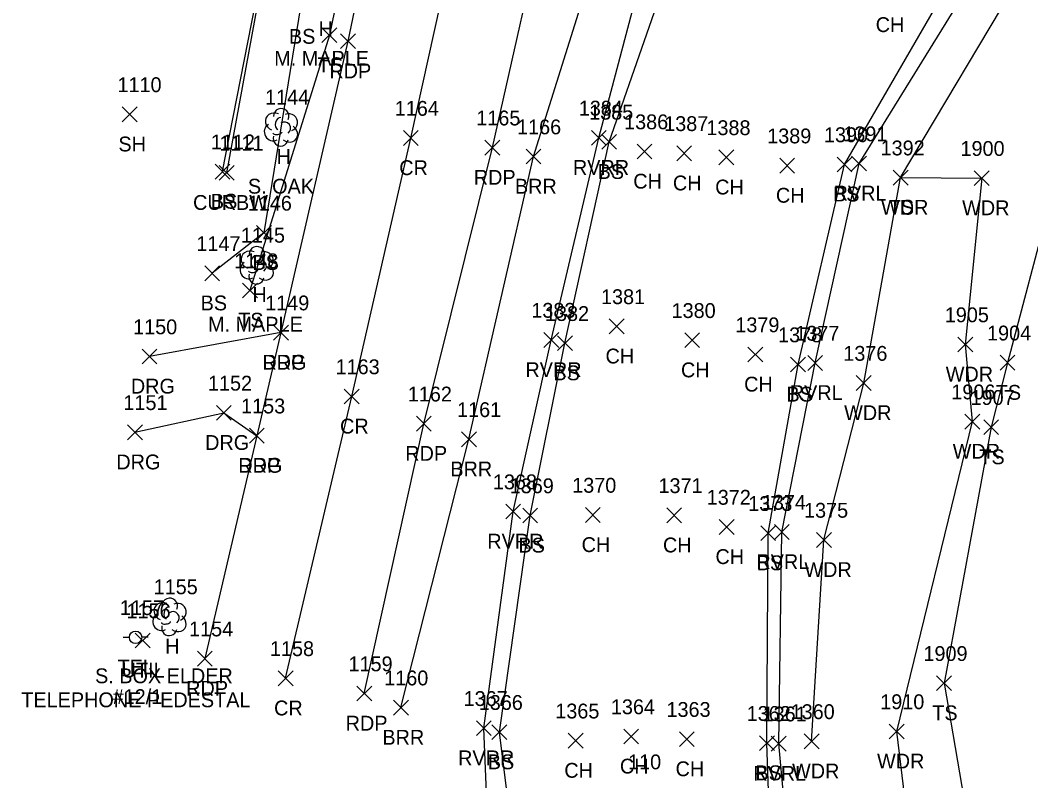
# Model space of a CAD drawing. Extents: x 1600395 to 1603269, y 874955 to 877143.
# Drawn here: x 1601626.7 to 1601763, y 875009.9 to 875112.5 of the extents above; entities that cross this region are included whole.
import ezdxf

# ---------------------------------------------------------------- set-up
doc = ezdxf.new("R2010")
doc.units = 0
for name, color, linetype in [('C_I', 7, 'Continuous'), ('L_A', 7, 'Continuous'), ('L_C', 7, 'Continuous'), ('L_I', 7, 'Continuous'), ('L_TIC', 7, 'Continuous'), ('LABL', 7, 'Continuous'), ('LAWA', 7, 'Continuous'), ('LAWE', 7, 'Continuous'), ('LELB', 7, 'Continuous'), ('LTD', 7, 'Continuous'), ('P_A', 7, 'Continuous'), ('P_I', 7, 'Continuous'), ('P_TIC', 7, 'Continuous'), ('PET', 7, 'Continuous'), ('PRC', 7, 'Continuous'), ('R_A', 7, 'Continuous'), ('R_I', 7, 'Continuous'), ('R_TIC', 7, 'Continuous'), ('RC', 7, 'Continuous'), ('RDG', 7, 'Continuous'), ('U_A', 7, 'Continuous'), ('U_C', 7, 'Continuous'), ('U_I', 7, 'Continuous'), ('UDEFAULT', 7, 'Continuous'), ('UP', 7, 'Continuous')]:
    doc.layers.add(name, color=color, linetype=linetype)

msp = doc.modelspace()

# ---------------------------------------------------------------- linework, layer by layer
at = {"layer": 'L_TIC'}
for points in [[(1601667.38, 875109.49), (1601669.38, 875111.49)], [(1601669.38, 875109.49), (1601667.38, 875111.49)], [(1601640.43, 875098.8), (1601642.43, 875100.8)], [(1601642.43, 875098.8), (1601640.43, 875100.8)], [(1601703.73, 875095.64), (1601705.73, 875097.64)], [(1601705.73, 875095.64), (1601703.73, 875097.64)], [(1601705.13, 875095.09), (1601707.13, 875097.09)], [(1601707.13, 875095.09), (1601705.13, 875097.09)], [(1601694.92, 875093.11), (1601696.92, 875095.11)], [(1601696.92, 875093.11), (1601694.92, 875095.11)], [(1601709.89, 875093.79), (1601711.89, 875095.79)], [(1601711.89, 875093.79), (1601709.89, 875095.79)], [(1601715.24, 875093.55), (1601717.24, 875095.55)], [(1601717.24, 875093.55), (1601715.24, 875095.55)], [(1601720.94, 875093), (1601722.94, 875095)], [(1601722.94, 875093), (1601720.94, 875095)], [(1601729.15, 875091.89), (1601731.15, 875093.89)], [(1601731.15, 875091.89), (1601729.15, 875093.89)], [(1601736.89, 875092.05), (1601738.89, 875094.05)], [(1601738.89, 875092.05), (1601736.89, 875094.05)], [(1601738.84, 875092.18), (1601740.84, 875094.18)], [(1601740.84, 875092.18), (1601738.84, 875094.18)], [(1601652.95, 875091.08), (1601654.95, 875093.08)], [(1601654.95, 875091.08), (1601652.95, 875093.08)], [(1601744.45, 875090.27), (1601746.45, 875092.27)], [(1601746.45, 875090.27), (1601744.45, 875092.27)], [(1601744.45, 875090.27), (1601746.45, 875092.27)], [(1601746.45, 875090.27), (1601744.45, 875092.27)], [(1601755.39, 875090.2), (1601757.39, 875092.2)], [(1601757.39, 875090.2), (1601755.39, 875092.2)], [(1601658.55, 875082.82), (1601660.55, 875084.82)], [(1601660.55, 875082.82), (1601658.55, 875084.82)], [(1601651.57, 875077.37), (1601653.57, 875079.37)], [(1601653.57, 875077.37), (1601651.57, 875079.37)], [(1601656.67, 875075.04), (1601658.67, 875077.04)], [(1601658.67, 875075.04), (1601656.67, 875077.04)], [(1601706.15, 875070.21), (1601708.15, 875072.21)], [(1601708.15, 875070.21), (1601706.15, 875072.21)], [(1601697.32, 875068.37), (1601699.32, 875070.37)], [(1601699.32, 875068.37), (1601697.32, 875070.37)], [(1601716.33, 875068.34), (1601718.33, 875070.34)], [(1601718.33, 875068.34), (1601716.33, 875070.34)], [(1601699.16, 875067.94), (1601701.16, 875069.94)], [(1601701.16, 875067.94), (1601699.16, 875069.94)], [(1601753.18, 875067.77), (1601755.18, 875069.77)], [(1601755.18, 875067.77), (1601753.18, 875069.77)], [(1601724.85, 875066.42), (1601726.85, 875068.42)], [(1601726.85, 875066.42), (1601724.85, 875068.42)], [(1601730.61, 875065.07), (1601732.61, 875067.07)], [(1601732.61, 875065.07), (1601730.61, 875067.07)], [(1601732.93, 875065.28), (1601734.93, 875067.28)], [(1601734.93, 875065.28), (1601732.93, 875067.28)], [(1601758.88, 875065.31), (1601760.88, 875067.31)], [(1601760.88, 875065.31), (1601758.88, 875067.31)], [(1601739.47, 875062.57), (1601741.47, 875064.57)], [(1601741.47, 875062.57), (1601739.47, 875064.57)], [(1601754.12, 875057.37), (1601756.12, 875059.37)], [(1601756.12, 875057.37), (1601754.12, 875059.37)], [(1601756.66, 875056.62), (1601758.66, 875058.62)], [(1601758.66, 875056.62), (1601756.66, 875058.62)], [(1601686.21, 875054.98), (1601688.21, 875056.98)], [(1601688.21, 875054.98), (1601686.21, 875056.98)], [(1601692.18, 875045.24), (1601694.18, 875047.24)], [(1601694.18, 875045.24), (1601692.18, 875047.24)], [(1601694.46, 875044.71), (1601696.46, 875046.71)], [(1601696.46, 875044.71), (1601694.46, 875046.71)], [(1601702.92, 875044.78), (1601704.92, 875046.78)], [(1601704.92, 875044.78), (1601702.92, 875046.78)], [(1601713.91, 875044.73), (1601715.91, 875046.73)], [(1601715.91, 875044.73), (1601713.91, 875046.73)], [(1601720.98, 875043.16), (1601722.98, 875045.16)], [(1601722.98, 875043.16), (1601720.98, 875045.16)], [(1601726.59, 875042.32), (1601728.59, 875044.32)], [(1601728.59, 875042.32), (1601726.59, 875044.32)], [(1601728.43, 875042.48), (1601730.43, 875044.48)], [(1601730.43, 875042.48), (1601728.43, 875044.48)], [(1601734.11, 875041.41), (1601736.11, 875043.41)], [(1601736.11, 875041.41), (1601734.11, 875043.41)], [(1601750.31, 875022.09), (1601752.31, 875024.09)], [(1601752.31, 875022.09), (1601750.31, 875024.09)], [(1601677.04, 875018.8), (1601679.04, 875020.8)], [(1601679.04, 875018.8), (1601677.04, 875020.8)], [(1601688.23, 875016.02), (1601690.23, 875018.02)], [(1601690.23, 875016.02), (1601688.23, 875018.02)], [(1601690.32, 875015.49), (1601692.32, 875017.49)], [(1601692.32, 875015.49), (1601690.32, 875017.49)], [(1601708.1, 875014.91), (1601710.1, 875016.91)], [(1601710.1, 875014.91), (1601708.1, 875016.91)], [(1601743.91, 875015.59), (1601745.91, 875017.59)], [(1601745.91, 875015.59), (1601743.91, 875017.59)], [(1601700.6, 875014.34), (1601702.6, 875016.34)], [(1601702.6, 875014.34), (1601700.6, 875016.34)], [(1601715.6, 875014.55), (1601717.6, 875016.55)], [(1601717.6, 875014.55), (1601715.6, 875016.55)], [(1601726.42, 875014.01), (1601728.42, 875016.01)], [(1601728.42, 875014.01), (1601726.42, 875016.01)], [(1601728, 875013.94), (1601730, 875015.94)], [(1601730, 875013.94), (1601728, 875015.94)], [(1601732.44, 875014.25), (1601734.44, 875016.25)], [(1601734.44, 875014.25), (1601732.44, 875016.25)]]:
    msp.add_lwpolyline(points, dxfattribs=at)
at = {"layer": 'LABL'}
msp.add_lwpolyline([(1601678.04, 875019.8), (1601687.21, 875055.98), (1601695.92, 875094.11), (1601706.34, 875127.39), (1601719.18, 875156.97), (1601728.75, 875176.92)], dxfattribs=at)
at = {"layer": 'LAWA'}
msp.add_lwpolyline([(1601733.44, 875015.25), (1601735.11, 875042.41), (1601740.47, 875063.57), (1601745.45, 875091.27), (1601756.39, 875091.2), (1601754.18, 875068.77), (1601755.12, 875058.37), (1601744.91, 875016.59), (1601747.26, 874996.94)], dxfattribs=at)
at = {"layer": 'LAWE'}
for points in [[(1601691.61, 874961.83), (1601690.19, 874993.06), (1601689.23, 875017.02), (1601693.18, 875046.24), (1601698.32, 875069.37), (1601704.73, 875096.64), (1601712.32, 875125.39), (1601726.38, 875151.58), (1601742.36, 875184.33), (1601749.84, 875201.82), (1601757.17, 875214.81), (1601763.47, 875228.29), (1601769.62, 875241.93), (1601778.23, 875255.27), (1601780.68, 875261.68), (1601794.38, 875288.12), (1601816.13, 875319.13), (1601836.1, 875339.54), (1601856.9, 875374.37), (1601871.66, 875400.7), (1601886.6, 875430.71)], [(1601732.59, 874962.16), (1601731.06, 874992.85), (1601729, 875014.94), (1601729.43, 875043.48), (1601733.93, 875066.28), (1601739.84, 875093.18), (1601757.34, 875121.49)]]:
    msp.add_lwpolyline(points, dxfattribs=at)
at = {"layer": 'LELB'}
for points in [[(1601699.55, 874960.02), (1601694.14, 874994.17), (1601691.32, 875016.49), (1601695.46, 875045.71), (1601700.16, 875068.94), (1601706.13, 875096.09), (1601716.31, 875125.25), (1601727.74, 875151.41), (1601744.12, 875184.77), (1601751.84, 875200.82), (1601755.99, 875200.42)], [(1601505.58, 875186.84), (1601543.5, 875188.16), (1601578.09, 875189.84), (1601619.87, 875193.15), (1601653.33, 875193.86), (1601668.35, 875196.11), (1601673.88, 875189.56), (1601676.77, 875181.49), (1601678.04, 875161.08), (1601676.09, 875147.88), (1601668.38, 875110.49), (1601657.67, 875076.04)], [(1601727.08, 874960.56), (1601728.14, 874994.47), (1601727.42, 875015.01), (1601727.59, 875043.32), (1601731.61, 875066.07), (1601737.89, 875093.05), (1601755.13, 875122.88), (1601766.48, 875138.81), (1601780.42, 875159.08), (1601801.25, 875183.04), (1601811.36, 875189.98)], [(1601745.45, 875091.27), (1601762.14, 875119.29), (1601773.1, 875139.17), (1601782.71, 875155.76), (1601813.34, 875184.04)], [(1601505.23, 875162.4), (1601544.12, 875168.6), (1601558.58, 875179.79), (1601582.31, 875176.11), (1601620.87, 875177.75), (1601653.84, 875181.08), (1601671.17, 875181.13), (1601672.7, 875160.58), (1601672.89, 875148.09), (1601664.48, 875114.32), (1601659.55, 875083.82), (1601652.57, 875078.37)], [(1601653.95, 875092.08), (1601660.35, 875124.64), (1601666.18, 875154.85)], [(1601765.68, 875088.22), (1601759.88, 875066.31), (1601757.66, 875057.62), (1601751.31, 875023.09), (1601756.38, 874993.66)]]:
    msp.add_lwpolyline(points, dxfattribs=at)
at = {"layer": 'LTD'}
for p, q in [((1601661.83, 875098.11), (1601661.83, 875098.11)), ((1601661.83, 875098.11), (1601661.83, 875098.11)), ((1601658.56, 875079.5), (1601658.56, 875079.5)), ((1601658.56, 875079.5), (1601658.56, 875079.5)), ((1601646.79, 875032.09), (1601646.79, 875032.09)), ((1601646.79, 875032.09), (1601646.79, 875032.09))]:
    msp.add_line(p, q, dxfattribs=at)
for centre in [(1601661.88, 875099.54), (1601658.61, 875080.93), (1601646.84, 875033.52)]:
    msp.add_arc(centre, 1.05, 335.5272, 180.9563, dxfattribs=at)
for centre, major_axis, ratio, start_param, end_param in [((1601661.04, 875098.78), (1.21, -0.51), 0.895232, 1.570796, 4.712389), ((1601662.87, 875098.69), (-1.14, -0.48), 0.949671, 1.570796, 4.712389), ((1601661.62, 875098.57), (-0.208, -0.792), 0.645439, 3.141593, 6.283185), ((1601662.33, 875097.94), (-0.5, 0.667), 0.989748, 3.141593, 6.283185), ((1601660.75, 875097.4), (0.58, -1.04), 0.959034, 3.141593, 6.283185), ((1601661.37, 875097.36), (-0.625, -0.083), 0.423636, 0, 3.141593), ((1601662.83, 875097.28), (-1.09, 0.79), 0.841452, 1.570796, 4.712389), ((1601661.83, 875096.61), (0.26, 1.06), 0.942809, 1.570796, 4.712389), ((1601657.77, 875080.16), (1.21, -0.51), 0.895232, 1.570796, 4.712389), ((1601659.6, 875080.08), (-1.14, -0.48), 0.949671, 1.570796, 4.712389), ((1601657.48, 875078.79), (0.58, -1.04), 0.959034, 3.141593, 6.283185), ((1601658.35, 875079.96), (-0.208, -0.792), 0.645439, 3.141593, 6.283185), ((1601659.06, 875079.33), (-0.5, 0.667), 0.989748, 3.141593, 6.283185), ((1601658.56, 875078), (0.26, 1.06), 0.942809, 1.570796, 4.712389), ((1601658.1, 875078.75), (-0.625, -0.083), 0.423636, 0, 3.141593), ((1601659.56, 875078.66), (-1.09, 0.79), 0.841452, 1.570796, 4.712389), ((1601646, 875032.75), (1.21, -0.51), 0.895232, 1.570796, 4.712389), ((1601646.59, 875032.55), (-0.208, -0.792), 0.645439, 3.141593, 6.283185), ((1601647.84, 875032.67), (-1.14, -0.48), 0.949671, 1.570796, 4.712389), ((1601645.71, 875031.38), (0.58, -1.04), 0.959034, 3.141593, 6.283185), ((1601647.29, 875031.92), (-0.5, 0.667), 0.989748, 3.141593, 6.283185), ((1601647.79, 875031.25), (-1.09, 0.79), 0.841452, 1.570796, 4.712389), ((1601646.79, 875030.59), (0.26, 1.06), 0.942809, 1.570796, 4.712389), ((1601646.34, 875031.34), (-0.625, -0.083), 0.423636, 0, 3.141593)]:
    msp.add_ellipse(centre, major_axis=major_axis, ratio=ratio, start_param=start_param, end_param=end_param, dxfattribs=at)
at = {"layer": 'P_TIC'}
for points in [[(1601669.89, 875108.66), (1601671.89, 875110.66)], [(1601671.89, 875108.66), (1601669.89, 875110.66)], [(1601678.38, 875095.61), (1601680.38, 875097.61)], [(1601680.38, 875095.61), (1601678.38, 875097.61)], [(1601689.37, 875094.31), (1601691.37, 875096.31)], [(1601691.37, 875094.31), (1601689.37, 875096.31)], [(1601660.85, 875069.37), (1601662.85, 875071.37)], [(1601662.85, 875069.37), (1601660.85, 875071.37)], [(1601670.39, 875060.76), (1601672.39, 875062.76)], [(1601672.39, 875060.76), (1601670.39, 875062.76)], [(1601680.13, 875057.08), (1601682.13, 875059.08)], [(1601682.13, 875057.08), (1601680.13, 875059.08)], [(1601657.6, 875055.47), (1601659.6, 875057.47)], [(1601659.6, 875055.47), (1601657.6, 875057.47)], [(1601650.57, 875025.41), (1601652.57, 875027.41)], [(1601652.57, 875025.41), (1601650.57, 875027.41)], [(1601661.48, 875022.75), (1601663.48, 875024.75)], [(1601663.48, 875022.75), (1601661.48, 875024.75)], [(1601672.09, 875020.7), (1601674.09, 875022.7)], [(1601674.09, 875020.7), (1601672.09, 875022.7)]]:
    msp.add_lwpolyline(points, dxfattribs=at)
at = {"layer": 'PET'}
for points in [[(1601673.09, 875021.7), (1601681.13, 875058.08), (1601690.37, 875095.31), (1601698.18, 875129.89), (1601704.68, 875160.33), (1601709.51, 875181.32), (1601714.92, 875193.42), (1601721.53, 875203.08), (1601729.11, 875210.61), (1601733.53, 875213.86), (1601739.73, 875217.72)], [(1601655.31, 875206.25), (1601666.28, 875201.03), (1601673.68, 875194.46), (1601676.81, 875189.05), (1601678.74, 875181.32), (1601679.6, 875161.13), (1601678.62, 875146.75), (1601670.89, 875109.66), (1601661.85, 875070.37), (1601658.6, 875056.47), (1601651.57, 875026.41)]]:
    msp.add_lwpolyline(points, dxfattribs=at)
at = {"layer": 'PRC'}
msp.add_lwpolyline([(1601662.48, 875023.75), (1601671.39, 875061.76), (1601679.38, 875096.61), (1601687.38, 875132.88), (1601692.14, 875158.22), (1601695.07, 875181.7), (1601696.1, 875195.08), (1601696.17, 875205.46), (1601695.28, 875211.43)], dxfattribs=at)
at = {"layer": 'R_TIC'}
for points in [[(1601653.53, 875090.92), (1601655.53, 875092.92)], [(1601655.53, 875090.92), (1601653.53, 875092.92)], [(1601660.85, 875069.37), (1601662.85, 875071.37)], [(1601662.85, 875069.37), (1601660.85, 875071.37)], [(1601643.11, 875066.15), (1601645.11, 875068.15)], [(1601645.11, 875066.15), (1601643.11, 875068.15)], [(1601653.13, 875058.55), (1601655.13, 875060.55)], [(1601655.13, 875058.55), (1601653.13, 875060.55)], [(1601641.15, 875055.93), (1601643.15, 875057.93)], [(1601643.15, 875055.93), (1601641.15, 875057.93)], [(1601657.6, 875055.47), (1601659.6, 875057.47)], [(1601659.6, 875055.47), (1601657.6, 875057.47)]]:
    msp.add_lwpolyline(points, dxfattribs=at)
at = {"layer": 'RC'}
msp.add_lwpolyline([(1601654.53, 875091.92), (1601660.57, 875124.77), (1601666.3, 875154.87)], dxfattribs=at)
at = {"layer": 'RDG'}
for points in [[(1601661.85, 875070.37), (1601644.11, 875067.15)], [(1601642.15, 875056.93), (1601654.13, 875059.55), (1601658.6, 875056.47)]]:
    msp.add_lwpolyline(points, dxfattribs=at)
at = {"layer": 'UDEFAULT'}
for points in [[(1601642.19, 875027.85), (1601644.19, 875029.85)], [(1601644.19, 875027.85), (1601642.19, 875029.85)]]:
    msp.add_lwpolyline(points, dxfattribs=at)
at = {"layer": 'UP'}
for p, q in [((1601640.58, 875029.28), (1601641.41, 875029.28)), ((1601642.24, 875029.28), (1601642.24, 875029.28)), ((1601643.91, 875029.28), (1601643.07, 875029.28)), ((1601643.07, 875029.28), (1601643.07, 875029.28)), ((1601643.91, 875029.28), (1601643.91, 875029.28))]:
    msp.add_line(p, q, dxfattribs=at)
msp.add_circle((1601642.24, 875029.28), 0.833, dxfattribs=at)

# ---------------------------------------------------------------- texts
at = {"layer": 'C_I'}
msp.add_text('110', height=2, dxfattribs=at).set_placement((1601708.68, 875011.48))
at = {"layer": 'L_A'}
for s, p in [('H', (1601666.92, 875110.36)), ('CH', (1601742.09, 875110.9)), ('BS', (1601662.93, 875109.32)), ('TS', (1601666.79, 875105.49)), ('SH', (1601639.92, 875094.8)), ('H', (1601661.26, 875093.11)), ('RVRR', (1601701.24, 875091.64)), ('BS', (1601704.57, 875091.09)), ('BRR', (1601693.41, 875089.11)), ('CH', (1601709.38, 875089.79)), ('CH', (1601714.73, 875089.55)), ('CH', (1601720.43, 875089)), ('CH', (1601728.63, 875087.89)), ('BS', (1601736.33, 875088.05)), ('RVRL', (1601736.41, 875088.18)), ('BS', (1601652.39, 875087.08)), ('WDR', (1601742.81, 875086.27)), ('TS', (1601743.85, 875086.27)), ('WDR', (1601753.75, 875086.2)), ('BS', (1601658, 875078.82)), ('H', (1601658, 875074.5)), ('BS', (1601651.01, 875073.37)), ('TS', (1601656.08, 875071.04)), ('CH', (1601705.64, 875066.21)), ('RVRR', (1601694.83, 875064.37)), ('BS', (1601698.6, 875063.94)), ('CH', (1601715.82, 875064.34)), ('WDR', (1601751.54, 875063.77)), ('CH', (1601724.34, 875062.42)), ('RVRL', (1601730.5, 875061.28)), ('TS', (1601758.29, 875061.31)), ('BS', (1601730.05, 875061.07)), ('WDR', (1601737.83, 875058.57)), ('WDR', (1601752.48, 875053.37)), ('TS', (1601756.07, 875052.62)), ('BRR', (1601684.7, 875050.98)), ('RVRR', (1601689.69, 875041.24)), ('CH', (1601702.41, 875040.78)), ('BS', (1601693.9, 875040.71)), ('CH', (1601713.39, 875040.73)), ('CH', (1601720.47, 875039.16)), ('RVRL', (1601725.99, 875038.48)), ('BS', (1601726.03, 875038.32)), ('WDR', (1601732.47, 875037.41)), ('H', (1601646.23, 875027.09)), ('TS', (1601749.72, 875018.09)), ('BRR', (1601675.53, 875014.8)), ('RVRR', (1601685.75, 875012.02)), ('BS', (1601689.76, 875011.49)), ('CH', (1601707.58, 875010.91)), ('WDR', (1601742.27, 875011.59)), ('CH', (1601700.08, 875010.34)), ('CH', (1601715.09, 875010.55)), ('RVRL', (1601725.57, 875009.94)), ('BS', (1601725.86, 875010.01)), ('WDR', (1601730.8, 875010.25))]:
    msp.add_text(s, height=2, dxfattribs=at).set_placement(p)
at = {"layer": 'L_C'}
for s, p in [('M. MAPLE', (1601660.94, 875106.36)), ('S. OAK', (1601657.39, 875089.11)), ('M. MAPLE', (1601652.01, 875070.5)), ('S. BOX ELDER', (1601636.77, 875023.09))]:
    msp.add_text(s, height=2, dxfattribs=at).set_placement(p)
at = {"layer": 'L_I'}
for s, p in [('1110', (1601639.79, 875102.8)), ('1144', (1601659.7, 875101.11)), ('1384', (1601702.03, 875099.64)), ('1385', (1601703.43, 875099.09)), ('1166', (1601693.7, 875097.11)), ('1386', (1601708.14, 875097.79)), ('1387', (1601713.55, 875097.55)), ('1388', (1601719.25, 875097)), ('1389', (1601727.45, 875095.89)), ('1390', (1601735.11, 875096.05)), ('1391', (1601737.72, 875096.18)), ('1112', (1601652.39, 875095.08)), ('1392', (1601742.75, 875094.27)), ('1392', (1601742.75, 875094.27)), ('1900', (1601753.53, 875094.2)), ('1146', (1601657.37, 875086.82)), ('1145', (1601656.44, 875082.5)), ('1147', (1601650.44, 875081.37)), ('1148', (1601655.54, 875079.04)), ('1381', (1601705.03, 875074.21)), ('1383', (1601695.63, 875072.37)), ('1380', (1601714.55, 875072.34)), ('1382', (1601697.47, 875071.94)), ('1905', (1601751.41, 875071.77)), ('1379', (1601723.15, 875070.42)), ('1378', (1601728.92, 875069.07)), ('1377', (1601731.24, 875069.28)), ('1904', (1601757.11, 875069.31)), ('1376', (1601737.72, 875066.57)), ('1906', (1601752.29, 875061.37)), ('1907', (1601754.89, 875060.62)), ('1161', (1601685.61, 875058.98)), ('1368', (1601690.44, 875049.24)), ('1369', (1601692.71, 875048.71)), ('1370', (1601701.14, 875048.78)), ('1371', (1601712.78, 875048.73)), ('1372', (1601719.29, 875047.16)), ('1373', (1601724.89, 875046.32)), ('1374', (1601726.73, 875046.48)), ('1375', (1601732.42, 875045.41)), ('1155', (1601644.67, 875035.09)), ('1909', (1601748.53, 875026.09)), ('1160', (1601675.78, 875022.8)), ('1367', (1601686.49, 875020.02)), ('1366', (1601688.53, 875019.49)), ('1910', (1601742.7, 875019.59)), ('1365', (1601698.86, 875018.34)), ('1364', (1601706.36, 875018.91)), ('1363', (1601713.86, 875018.55)), ('1362', (1601724.68, 875018.01)), ('1361', (1601726.83, 875017.94)), ('1360', (1601730.61, 875018.25))]:
    msp.add_text(s, height=2, dxfattribs=at).set_placement(p)
at = {"layer": 'P_A'}
for s, p in [('RDP', (1601668.38, 875104.66)), ('CR', (1601677.81, 875091.61)), ('RDP', (1601687.86, 875090.31)), ('RDP', (1601659.34, 875065.37)), ('CR', (1601669.82, 875056.76)), ('RDP', (1601678.62, 875053.08)), ('RDP', (1601656.09, 875051.47)), ('RDP', (1601649.06, 875021.41)), ('CR', (1601660.92, 875018.75)), ('RDP', (1601670.58, 875016.7))]:
    msp.add_text(s, height=2, dxfattribs=at).set_placement(p)
at = {"layer": 'P_I'}
for s, p in [('1164', (1601677.2, 875099.61)), ('1165', (1601688.2, 875098.31)), ('1149', (1601659.72, 875073.37)), ('1163', (1601669.22, 875064.76)), ('1162', (1601678.96, 875061.08)), ('1153', (1601656.47, 875059.47)), ('1154', (1601649.45, 875029.41)), ('1158', (1601660.36, 875026.75)), ('1159', (1601670.96, 875024.7))]:
    msp.add_text(s, height=2, dxfattribs=at).set_placement(p)
at = {"layer": 'R_A'}
for s, p in [('CURBW', (1601649.99, 875086.92)), ('DRG', (1601659.34, 875065.37)), ('DRG', (1601641.6, 875062.15)), ('DRG', (1601651.62, 875054.55)), ('DRG', (1601639.64, 875051.93)), ('DRG', (1601656.09, 875051.47))]:
    msp.add_text(s, height=2, dxfattribs=at).set_placement(p)
at = {"layer": 'R_I'}
for s, p in [('1111', (1601653.54, 875094.92)), ('1149', (1601659.72, 875073.37)), ('1150', (1601641.9, 875070.15)), ('1152', (1601652, 875062.55)), ('1151', (1601640.59, 875059.93)), ('1153', (1601656.47, 875059.47))]:
    msp.add_text(s, height=2, dxfattribs=at).set_placement(p)
at = {"layer": 'U_A'}
for s, p in [('TEL', (1601639.8, 875024.28)), ('UTIL', (1601640.36, 875023.85))]:
    msp.add_text(s, height=2, dxfattribs=at).set_placement(p)
at = {"layer": 'U_C'}
for s, p in [('#12/1', (1601639.14, 875020.28)), ('TELEPHONE PEDESTAL', (1601626.82, 875019.85))]:
    msp.add_text(s, height=2, dxfattribs=at).set_placement(p)
at = {"layer": 'U_I'}
for s, p in [('1157', (1601640.11, 875032.28)), ('1156', (1601641.01, 875031.85))]:
    msp.add_text(s, height=2, dxfattribs=at).set_placement(p)

doc.saveas('drawing.dxf')
